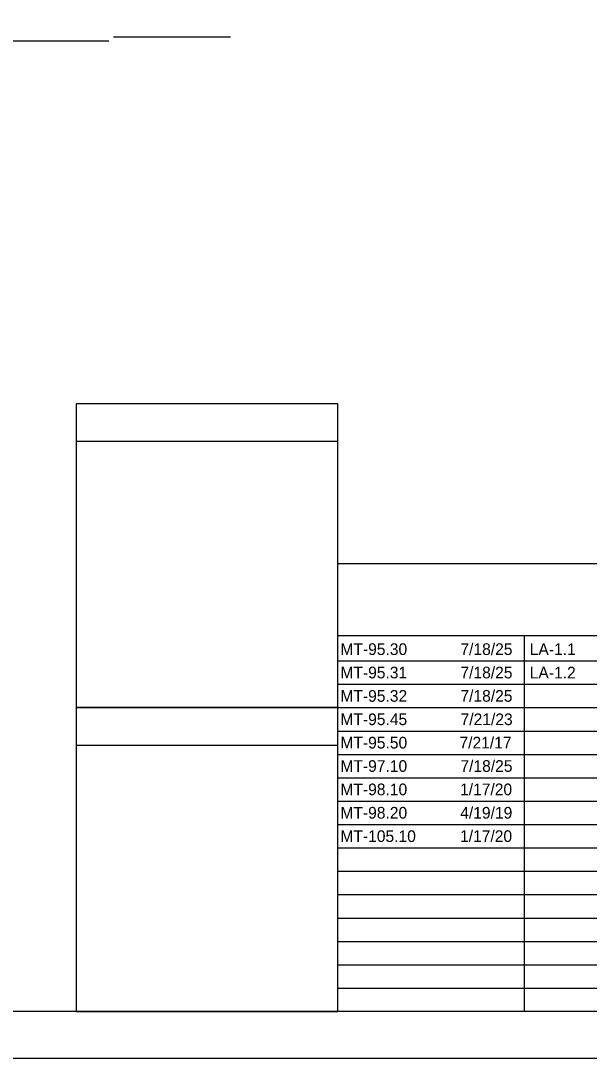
# Model space of a CAD drawing. Extents: x 0 to 34, y 0 to 22.
# Drawn here: x 6.76 to 12.84, y 0 to 11.1 of the extents above; entities that cross this region are included whole.
import ezdxf

# ---------------------------------------------------------------- set-up
doc = ezdxf.new("R2010")
doc.units = 0
for name, color, linetype in [('Default', 7, 'Continuous'), ('SH_Border', 7, 'Continuous'), ('SH_Cut_Line', 7, 'Continuous'), ('SH_Data', 7, 'Continuous')]:
    doc.layers.add(name, color=color, linetype=linetype)

msp = doc.modelspace()

# ---------------------------------------------------------------- linework, layer by layer
at = {"layer": 'SH_Border'}
msp.add_lwpolyline([(1.5, 21.5), (33.5, 21.5), (33.5, 0.5), (1.5, 0.5)], close=True, dxfattribs=at)
at = {"layer": 'SH_Cut_Line'}
msp.add_lwpolyline([(0, 0), (34, 0), (34, 22), (0, 22)], close=True, dxfattribs=at)
at = {"layer": 'SH_Data'}
for p, q in [((7.7, 10.877), (3.347, 10.877)), ((9, 10.922), (7.75, 10.922)), ((7.35, 6.6), (10.15, 6.6)), ((10.15, 5.292), (23.6, 5.292)), ((10.15, 0.5), (10.15, 5.292)), ((10.15, 4.521), (23.6, 4.521)), ((12.15, 0.5), (12.15, 4.521)), ((10.15, 4.25), (23.6, 4.25)), ((10.15, 4), (23.6, 4)), ((10.15, 3.75), (23.6, 3.75)), ((10.15, 3.5), (23.6, 3.5)), ((7.35, 3.35), (10.15, 3.35)), ((10.15, 3.25), (23.6, 3.25)), ((10.15, 3), (23.6, 3)), ((10.15, 2.75), (23.6, 2.75)), ((10.15, 2.5), (23.6, 2.5)), ((10.15, 2.25), (23.6, 2.25)), ((10.15, 2), (23.6, 2)), ((10.15, 1.75), (23.6, 1.75)), ((10.15, 1.5), (23.6, 1.5)), ((10.15, 1.25), (23.6, 1.25)), ((10.15, 1), (23.6, 1)), ((10.15, 0.75), (23.6, 0.75))]:
    msp.add_line(p, q, dxfattribs=at)
for points in [[(10.15, 7), (7.35, 7), (7.35, 3.75), (10.15, 3.75)], [(10.15, 3.75), (7.35, 3.75), (7.35, 0.5), (10.15, 0.5)]]:
    msp.add_lwpolyline(points, close=True, dxfattribs=at)

# ---------------------------------------------------------------- texts
at = {"layer": 'Default'}
for s, p in [('MT-95.30', (10.178, 4.313)), ('7/18/25', (11.463, 4.313)), ('LA-1.1', (12.205, 4.312)), ('MT-95.31', (10.178, 4.063)), ('7/18/25', (11.463, 4.063)), ('LA-1.2', (12.205, 4.062)), ('MT-95.32', (10.178, 3.813)), ('7/18/25', (11.463, 3.813)), ('MT-95.45', (10.178, 3.563)), ('7/21/23', (11.465, 3.563)), ('MT-95.50', (10.178, 3.313)), ('7/21/17', (11.453, 3.313)), ('MT-97.10', (10.178, 3.063)), ('7/18/25', (11.463, 3.063)), ('MT-98.10', (10.178, 2.813)), ('1/17/20', (11.459, 2.813)), ('MT-98.20', (10.178, 2.563)), ('4/19/19', (11.461, 2.563)), ('1/17/20', (11.459, 2.313)), ('MT-105.10', (10.178, 2.313))]:
    msp.add_text(s, height=0.125, dxfattribs=at).set_placement(p)

doc.saveas('drawing.dxf')
